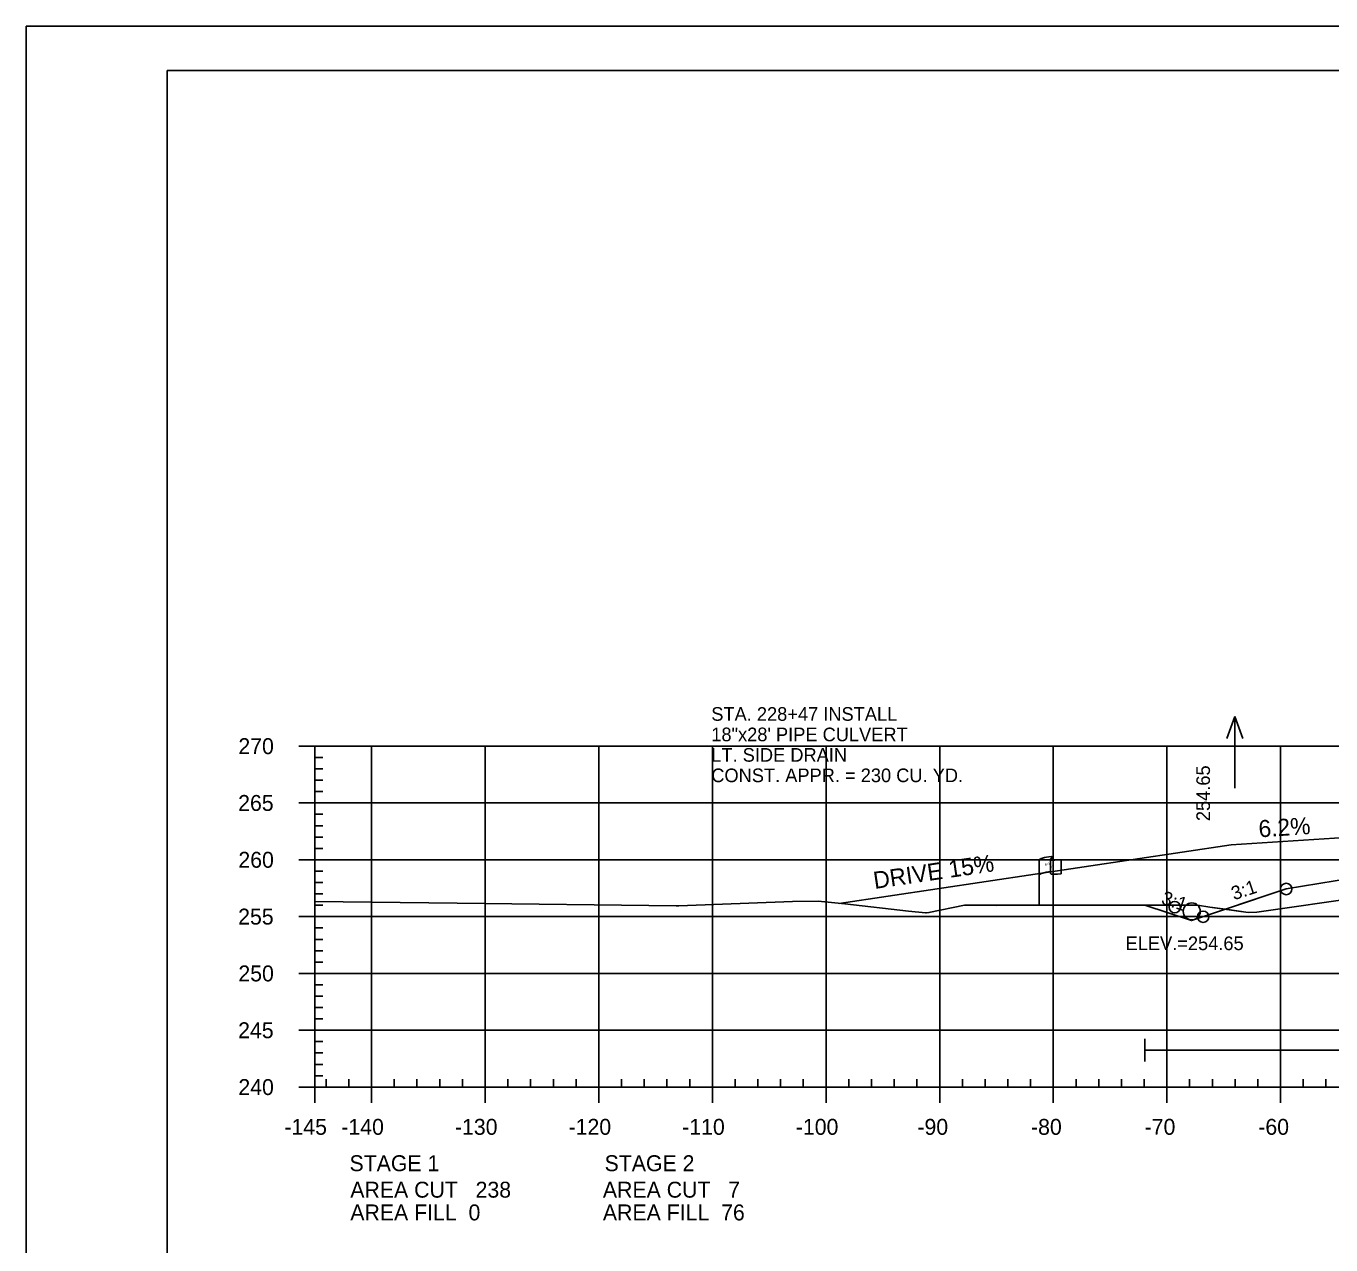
# Model space of a CAD drawing. Extents: x 1365647 to 1367999, y 387113 to 400173.
# Drawn here: x 1365723.7 to 1365838.5, y 391958.9 to 392066.2 of the extents above; entities that cross this region are included whole.
import ezdxf

# ---------------------------------------------------------------- set-up
doc = ezdxf.new("R2010")
doc.units = 0
for name, color, linetype in [('E_Existing ROW', 7, 'Continuous'), ('R_Axis', 7, 'Continuous'), ('R_Axis Annot', 7, 'Continuous'), ('R_Border', 7, 'Continuous'), ('R_Border Notes', 7, 'Continuous'), ('R_Contours', 7, 'Continuous'), ('R_Draft', 7, 'Continuous'), ('R_Drive', 7, 'Continuous'), ('R_Exist Surface', 7, 'Continuous'), ('R_Fin Surface', 7, 'Continuous'), ('R_Fin Surface Annot', 7, 'Continuous'), ('R_Grid', 7, 'Continuous'), ('R_No Plot', 7, 'Continuous'), ('R_Water', 7, 'Continuous'), ('R_Water Annot', 7, 'Continuous')]:
    doc.layers.add(name, color=color, linetype=linetype)

msp = doc.modelspace()

# ---------------------------------------------------------------- linework, layer by layer
at = {"layer": 'E_Existing ROW'}
for p, q in [((1365812.85, 391988.81), (1365812.85, 391992.76)), ((1365813.85, 391992.86), (1365813.85, 391992.84)), ((1365813.85, 391992.84), (1365813.85, 391991.62)), ((1365814.01, 391993.01), (1365814.01, 391992.77)), ((1365814.78, 391992.82), (1365814.78, 391991.58))]:
    msp.add_line(p, q, dxfattribs=at)
for centre, radius, start, end in [((1365813.94, 391993.01), 0.0783, 263.0712, 93.9564), ((1365813.92, 391992.86), 0.078, 88.6458, 274.2828), ((1365813.92, 391991.62), 0.0783, 180, 273.9564)]:
    msp.add_arc(centre, radius, start, end, dxfattribs=at)
for centre, major_axis, ratio, start_param, end_param in [((1365814.43, 391992.81), (-1.58, -0.04), 0.19887, 5.030368, 6.283185), ((1365815.14, 391992.92), (-1.23, -0.13), 0.052933, 0.159456, 1.268315), ((1365814.43, 391991.49), (-1.58, -0.04), 0.19887, 5.083035, 6.194897), ((1365815.14, 391991.68), (-1.23, -0.13), 0.052933, 0.159456, 1.268315)]:
    msp.add_ellipse(centre, major_axis=major_axis, ratio=ratio, start_param=start_param, end_param=end_param, dxfattribs=at)
at = {"layer": 'R_Axis'}
for p, q in [((1365747.69, 392002.81), (1365749.09, 392002.81)), ((1365749.09, 391972.81), (1365749.09, 392002.81)), ((1365749.09, 392001.81), (1365749.79, 392001.81)), ((1365749.09, 392000.81), (1365749.79, 392000.81)), ((1365749.09, 391999.81), (1365749.79, 391999.81)), ((1365749.09, 391998.81), (1365749.79, 391998.81)), ((1365747.69, 391997.81), (1365749.09, 391997.81)), ((1365749.09, 391996.81), (1365749.79, 391996.81)), ((1365749.09, 391995.81), (1365749.79, 391995.81)), ((1365749.09, 391994.81), (1365749.79, 391994.81)), ((1365749.09, 391993.81), (1365749.79, 391993.81)), ((1365747.69, 391992.81), (1365749.09, 391992.81)), ((1365749.09, 391991.81), (1365749.79, 391991.81)), ((1365749.09, 391990.81), (1365749.79, 391990.81)), ((1365749.09, 391989.81), (1365749.79, 391989.81)), ((1365749.09, 391988.81), (1365749.79, 391988.81)), ((1365747.69, 391987.81), (1365749.09, 391987.81)), ((1365749.09, 391986.81), (1365749.79, 391986.81)), ((1365749.09, 391985.81), (1365749.79, 391985.81)), ((1365749.09, 391984.81), (1365749.79, 391984.81)), ((1365747.69, 391982.81), (1365749.09, 391982.81)), ((1365749.09, 391983.81), (1365749.79, 391983.81)), ((1365749.09, 391981.81), (1365749.79, 391981.81)), ((1365749.09, 391980.81), (1365749.79, 391980.81)), ((1365749.09, 391979.81), (1365749.79, 391979.81)), ((1365749.09, 391978.81), (1365749.79, 391978.81)), ((1365747.69, 391977.81), (1365749.09, 391977.81)), ((1365749.09, 391976.81), (1365749.79, 391976.81)), ((1365749.09, 391975.81), (1365749.79, 391975.81)), ((1365749.09, 391974.81), (1365749.79, 391974.81)), ((1365749.09, 391973.81), (1365749.79, 391973.81)), ((1365747.69, 391972.81), (1365749.09, 391972.81)), ((1365749.09, 391972.81), (1365749.09, 391973.51)), ((1365749.09, 391972.81), (1366039.09, 391972.81)), ((1365749.09, 391971.41), (1365749.09, 391972.81)), ((1365750.09, 391972.81), (1365750.09, 391973.51)), ((1365752.09, 391972.81), (1365752.09, 391973.51)), ((1365754.09, 391971.41), (1365754.09, 391972.81)), ((1365756.09, 391972.81), (1365756.09, 391973.51)), ((1365758.09, 391972.81), (1365758.09, 391973.51)), ((1365760.09, 391972.81), (1365760.09, 391973.51)), ((1365762.09, 391972.81), (1365762.09, 391973.51)), ((1365764.09, 391971.41), (1365764.09, 391972.81)), ((1365766.09, 391972.81), (1365766.09, 391973.51)), ((1365768.09, 391972.81), (1365768.09, 391973.51)), ((1365770.09, 391972.81), (1365770.09, 391973.51)), ((1365772.09, 391972.81), (1365772.09, 391973.51)), ((1365774.09, 391971.41), (1365774.09, 391972.81)), ((1365776.09, 391972.81), (1365776.09, 391973.51)), ((1365778.09, 391972.81), (1365778.09, 391973.51)), ((1365780.09, 391972.81), (1365780.09, 391973.51)), ((1365782.09, 391972.81), (1365782.09, 391973.51)), ((1365784.09, 391971.41), (1365784.09, 391972.81)), ((1365786.09, 391972.81), (1365786.09, 391973.51)), ((1365788.09, 391972.81), (1365788.09, 391973.51)), ((1365790.09, 391972.81), (1365790.09, 391973.51)), ((1365792.09, 391972.81), (1365792.09, 391973.51)), ((1365794.09, 391971.41), (1365794.09, 391972.81)), ((1365796.09, 391972.81), (1365796.09, 391973.51)), ((1365798.09, 391972.81), (1365798.09, 391973.51)), ((1365800.09, 391972.81), (1365800.09, 391973.51)), ((1365802.09, 391972.81), (1365802.09, 391973.51)), ((1365804.09, 391971.41), (1365804.09, 391972.81)), ((1365806.09, 391972.81), (1365806.09, 391973.51)), ((1365808.09, 391972.81), (1365808.09, 391973.51)), ((1365810.09, 391972.81), (1365810.09, 391973.51)), ((1365812.09, 391972.81), (1365812.09, 391973.51)), ((1365814.09, 391971.41), (1365814.09, 391972.81)), ((1365816.09, 391972.81), (1365816.09, 391973.51)), ((1365818.09, 391972.81), (1365818.09, 391973.51)), ((1365820.09, 391972.81), (1365820.09, 391973.51)), ((1365822.09, 391972.81), (1365822.09, 391973.51)), ((1365824.09, 391971.41), (1365824.09, 391972.81)), ((1365826.09, 391972.81), (1365826.09, 391973.51)), ((1365828.09, 391972.81), (1365828.09, 391973.51)), ((1365830.09, 391972.81), (1365830.09, 391973.51)), ((1365832.09, 391972.81), (1365832.09, 391973.51)), ((1365834.09, 391971.41), (1365834.09, 391972.81)), ((1365836.09, 391972.81), (1365836.09, 391973.51)), ((1365838.09, 391972.81), (1365838.09, 391973.51))]:
    msp.add_line(p, q, dxfattribs=at)
at = {"layer": 'R_Border'}
for p, q in [((1365736.09, 392062.27), (1366052.27, 392062.27)), ((1365736.09, 391856.81), (1365736.09, 392062.27))]:
    msp.add_line(p, q, dxfattribs=at)
at = {"layer": 'R_Contours'}
for points in [[(1365829.24, 391988.46), (1365831.24, 391988.17), (1365832.01, 391988.2), (1365841.41, 391989.55), (1365842.93, 391989.88), (1365845.07, 391989.88), (1365848.98, 391989.86), (1365852.47, 391989.87), (1365856.84, 391989.7), (1365858.85, 391989.6), (1365860.37, 391989.51), (1365862.36, 391989.42), (1365865.87, 391989.24), (1365866.59, 391989.2), (1365867.48, 391989.34), (1365869.43, 391989.65), (1365871.15, 391990.02), (1365874.52, 391990.69), (1365862.59, 391991.86), (1365841.78, 391991.44), (1365834.59, 391990.24)], [(1365822.16, 391988.82), (1365826.79, 391988.83), (1365827.88, 391988.65), (1365829.24, 391988.46), (1365826.24, 391987.46)]]:
    msp.add_lwpolyline(points, close=True, dxfattribs=at)
at = {"layer": 'R_Drive'}
for p, q in [((1365829.75, 391994.14), (1365839.74, 391994.76)), ((1365795.24, 391988.96), (1365829.75, 391994.14)), ((1365809.09, 391988.73), (1365809.09, 391988.73))]:
    msp.add_line(p, q, dxfattribs=at)
at = {"layer": 'R_Exist Surface'}
msp.add_lwpolyline([(1365749.09, 391989.15), (1365749.11, 391989.15), (1365761.64, 391989), (1365780.89, 391988.77), (1365781.13, 391988.77), (1365791.13, 391989.13), (1365793.4, 391989.16), (1365795.75, 391988.92), (1365801.36, 391988.3), (1365802.83, 391988.15), (1365802.94, 391988.14), (1365803.14, 391988.17), (1365806.27, 391988.81), (1365812.97, 391988.81), (1365826.79, 391988.83), (1365827.88, 391988.65), (1365831.24, 391988.17), (1365832.01, 391988.2), (1365841.41, 391989.55)], dxfattribs=at)
at = {"layer": 'R_Fin Surface'}
msp.add_lwpolyline([(1365822.16, 391988.82), (1365826.24, 391987.46), (1365834.59, 391990.24), (1365841.78, 391991.44), (1365856.59, 391993.91), (1365862.59, 391993.32), (1365864.59, 391993.13), (1365894.09, 391990.24), (1365923.59, 391987.34), (1365925.59, 391987.15), (1365931.59, 391986.56), (1365953.01, 391982.99), (1365953.59, 391982.89), (1365958.12, 391981.38), (1365981.82, 391989.28)], dxfattribs=at)
at = {"layer": 'R_Grid'}
for p, q in [((1365749.09, 392002.81), (1366039.09, 392002.81)), ((1365749.09, 391972.81), (1365749.09, 392002.81)), ((1365754.09, 391972.81), (1365754.09, 392002.81)), ((1365764.09, 391972.81), (1365764.09, 392002.81)), ((1365774.09, 391972.81), (1365774.09, 392002.81)), ((1365784.09, 391972.81), (1365784.09, 392002.81)), ((1365794.09, 391972.81), (1365794.09, 392002.81)), ((1365804.09, 391972.81), (1365804.09, 392002.81)), ((1365814.09, 391972.81), (1365814.09, 392002.81)), ((1365824.09, 391972.81), (1365824.09, 392002.81)), ((1365834.09, 391972.81), (1365834.09, 392002.81)), ((1365749.09, 391997.81), (1366039.09, 391997.81)), ((1365749.09, 391992.81), (1366039.09, 391992.81)), ((1365749.09, 391987.81), (1366039.09, 391987.81)), ((1365749.09, 391982.81), (1366039.09, 391982.81)), ((1365749.09, 391977.81), (1366039.09, 391977.81)), ((1365749.09, 391972.81), (1366039.09, 391972.81))]:
    msp.add_line(p, q, dxfattribs=at)
at = {"layer": 'R_No Plot'}
msp.add_line((1365723.69, 392066.17), (1366057.03, 392066.17), dxfattribs=at)
msp.add_lwpolyline([(1365723.69, 392066.17), (1366057.03, 392066.17), (1366057.03, 391852.83), (1365723.69, 391852.83)], close=True, dxfattribs=at)
for centre in [(1365834.59, 391990.24), (1365834.59, 391990.24), (1365834.59, 391990.24), (1365834.59, 391990.24), (1365834.59, 391990.24), (1365824.78, 391988.64), (1365824.78, 391988.64), (1365827.28, 391987.8), (1365827.28, 391987.8)]:
    msp.add_circle(centre, 0.5, dxfattribs=at)
at = {"layer": 'R_Water'}
for p, q in [((1365822.16, 391975.06), (1365822.16, 391977.06)), ((1365822.16, 391976.06), (1365882.56, 391976.06))]:
    msp.add_line(p, q, dxfattribs=at)
msp.add_circle((1365826.28, 391988.27), 0.75, dxfattribs=at)
at = {"layer": 'R_Water Annot'}
for p, q in [((1365830.06, 392005.41), (1365829.36, 392003.49)), ((1365830.06, 391999.12), (1365830.06, 392005.41)), ((1365830.06, 392005.41), (1365830.76, 392003.49))]:
    msp.add_line(p, q, dxfattribs=at)

# ---------------------------------------------------------------- texts
at = {"layer": 'E_Existing ROW'}
for s, height, rotation, p in [('R ', 0.2, 9.9884, (1365813.37, 391992.26)), (' O', 0.2, 9.9884, (1365813.52, 391992.31)), ('W', 0.2, 351.1788, (1365813.85, 391992.14)), ('DWB 11-9-07', 0.001, 90, (1365814.01, 391992.77)), ('DWB 11-9-07', 0.001, 5.0717, (1365814.77, 391991.58)), ('DWB 11-9-07', 0.001, 90, (1365812.85, 391988.81))]:
    msp.add_text(s, height=height, rotation=rotation, dxfattribs=at).set_placement(p)
at = {"layer": 'R_Axis Annot'}
for s, p in [('270', (1365742.37, 392002.11)), ('265', (1365742.35, 391997.11)), ('260', (1365742.37, 391992.11)), ('255', (1365742.35, 391987.11)), ('250', (1365742.37, 391982.11)), ('245', (1365742.35, 391977.11)), ('240', (1365742.37, 391972.11)), ('-145', (1365746.42, 391968.61)), ('-140', (1365751.43, 391968.61)), ('-130', (1365761.43, 391968.61)), ('-120', (1365771.43, 391968.61)), ('-110', (1365781.43, 391968.61)), ('-100', (1365791.43, 391968.61)), ('-90', (1365802.13, 391968.61)), ('-80', (1365812.13, 391968.61)), ('-70', (1365822.13, 391968.61)), ('-60', (1365832.13, 391968.61)), ('STAGE 1', (1365752.15, 391965.41)), ('STAGE 2', (1365774.6, 391965.41)), ('AREA CUT   238', (1365752.22, 391963.08)), ('AREA CUT   7', (1365774.45, 391963.08)), ('AREA FILL  0', (1365752.22, 391961.08)), ('AREA FILL  76', (1365774.45, 391961.08))]:
    msp.add_text(s, height=1.4, dxfattribs=at).set_placement(p)
at = {"layer": 'R_Border Notes'}
msp.add_text('ELEV.=254.65', height=1.2, dxfattribs=at).set_placement((1365820.45, 391984.86))
at = {"layer": 'R_Draft'}
for s, p in [('STA. 228+47 INSTALL ', (1365783.99, 392005.04)), ('18"x28\' PIPE CULVERT', (1365783.99, 392003.24)), ('LT. SIDE DRAIN', (1365783.99, 392001.44)), ('CONST. APPR. = 230 CU. YD.', (1365783.99, 391999.64))]:
    msp.add_text(s, height=1.2, rotation=360, dxfattribs=at).set_placement(p)
at = {"layer": 'R_Drive'}
for s, rotation, p in [('6.2%', 3.6881, (1365832.2, 391994.78)), ('DRIVE 15%', 8.437, (1365798.37, 391990.24))]:
    msp.add_text(s, height=1.5, rotation=rotation, dxfattribs=at).set_placement(p)
at = {"layer": 'R_Fin Surface Annot'}
for s, rotation, p in [('254.65', 90, (1365827.88, 391996.21)), ('3:1', 18.4349, (1365829.99, 391989.24)), ('3:1', 341.5651, (1365823.52, 391988.96))]:
    msp.add_text(s, height=1.2, rotation=rotation, dxfattribs=at).set_placement(p)

doc.saveas('drawing.dxf')
